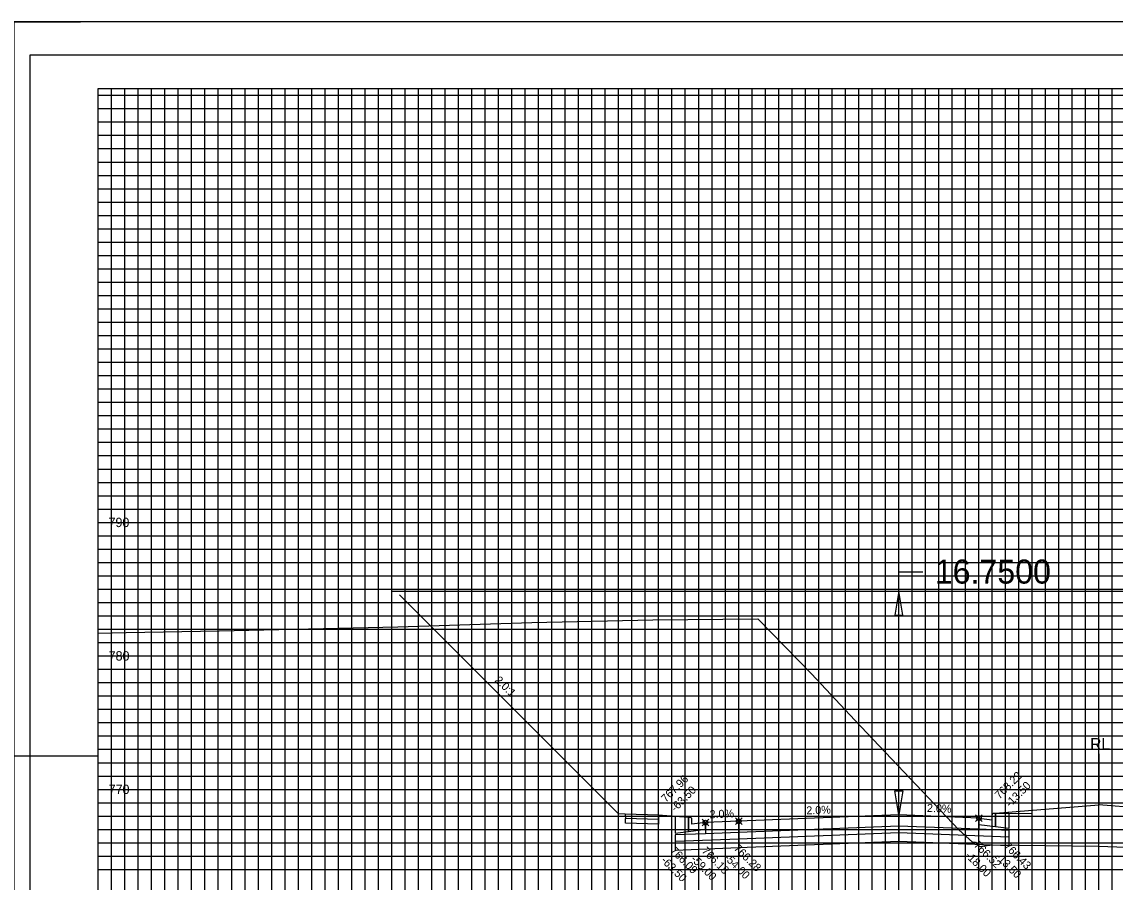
# Model space of a CAD drawing. Extents: x 578243 to 601557, y 174899 to 175559.
# Drawn here: x 600198.4 to 600362.3, y 174989.9 to 175118.8 of the extents above; entities that cross this region are included whole.
import ezdxf

# ---------------------------------------------------------------- set-up
doc = ezdxf.new("R2010")
doc.units = 0
for name, color, linetype in [('E_PROF_Grid', 7, 'Continuous'), ('E_PROF_GridMin', 7, 'Continuous'), ('P_CRDR_Label', 7, 'Continuous'), ('P_CRDR_Link', 7, 'Continuous'), ('P_E_XS_Ground', 7, 'Continuous'), ('P_RW_SlopeIntercepts', 7, 'Continuous'), ('P_XS_Text', 7, 'Continuous'), ('PLT_Sheet_Border', 7, 'Continuous'), ('PLT_Sheet_Info', 7, 'Continuous')]:
    doc.layers.add(name, color=color, linetype=linetype)

msp = doc.modelspace()

# ---------------------------------------------------------------- linework, layer by layer
at = {"layer": 'E_PROF_Grid'}
for p, q in [((600219.84, 174913.8), (600219.84, 175108.8)), ((600229.84, 174913.8), (600229.84, 175108.8)), ((600239.84, 174913.8), (600239.84, 175108.8)), ((600249.84, 174913.8), (600249.84, 175108.8)), ((600259.84, 174913.8), (600259.84, 175108.8)), ((600269.84, 174913.8), (600269.84, 175108.8)), ((600279.84, 174913.8), (600279.84, 175108.8)), ((600289.84, 174913.8), (600289.84, 175108.8)), ((600299.84, 174913.8), (600299.84, 175108.8)), ((600309.84, 174913.8), (600309.84, 175108.8)), ((600319.84, 174913.8), (600319.84, 175108.8)), ((600329.84, 174913.8), (600329.84, 175108.8)), ((600339.84, 174913.8), (600339.84, 175108.8)), ((600349.84, 174913.8), (600349.84, 175108.8)), ((600359.84, 174913.8), (600359.84, 175108.8)), ((600209.84, 175103.8), (600524.84, 175103.8)), ((600209.84, 175093.8), (600524.84, 175093.8)), ((600209.84, 175083.8), (600524.84, 175083.8)), ((600209.84, 175073.8), (600524.84, 175073.8)), ((600209.84, 175063.8), (600524.84, 175063.8)), ((600209.84, 175053.8), (600524.84, 175053.8)), ((600209.84, 175043.8), (600524.84, 175043.8)), ((600209.84, 175033.8), (600524.84, 175033.8)), ((600209.84, 175023.8), (600524.84, 175023.8)), ((600209.84, 175013.8), (600524.84, 175013.8)), ((600209.84, 175003.8), (600524.84, 175003.8)), ((600209.84, 174993.8), (600524.84, 174993.8))]:
    msp.add_line(p, q, dxfattribs=at)
at = {"layer": 'E_PROF_GridMin'}
for p, q in [((600211.84, 174913.8), (600211.84, 175108.8)), ((600213.84, 174913.8), (600213.84, 175108.8)), ((600215.84, 174913.8), (600215.84, 175108.8)), ((600217.84, 174913.8), (600217.84, 175108.8)), ((600221.84, 174913.8), (600221.84, 175108.8)), ((600223.84, 174913.8), (600223.84, 175108.8)), ((600225.84, 174913.8), (600225.84, 175108.8)), ((600227.84, 174913.8), (600227.84, 175108.8)), ((600231.84, 174913.8), (600231.84, 175108.8)), ((600233.84, 174913.8), (600233.84, 175108.8)), ((600235.84, 174913.8), (600235.84, 175108.8)), ((600237.84, 174913.8), (600237.84, 175108.8)), ((600241.84, 174913.8), (600241.84, 175108.8)), ((600243.84, 174913.8), (600243.84, 175108.8)), ((600245.84, 174913.8), (600245.84, 175108.8)), ((600247.84, 174913.8), (600247.84, 175108.8)), ((600251.84, 174913.8), (600251.84, 175108.8)), ((600253.84, 174913.8), (600253.84, 175108.8)), ((600255.84, 174913.8), (600255.84, 175108.8)), ((600257.84, 174913.8), (600257.84, 175108.8)), ((600261.84, 174913.8), (600261.84, 175108.8)), ((600263.84, 174913.8), (600263.84, 175108.8)), ((600265.84, 174913.8), (600265.84, 175108.8)), ((600267.84, 174913.8), (600267.84, 175108.8)), ((600271.84, 174913.8), (600271.84, 175108.8)), ((600273.84, 174913.8), (600273.84, 175108.8)), ((600275.84, 174913.8), (600275.84, 175108.8)), ((600277.84, 174913.8), (600277.84, 175108.8)), ((600281.84, 174913.8), (600281.84, 175108.8)), ((600283.84, 174913.8), (600283.84, 175108.8)), ((600285.84, 174913.8), (600285.84, 175108.8)), ((600287.84, 174913.8), (600287.84, 175108.8)), ((600291.84, 174913.8), (600291.84, 175108.8)), ((600293.84, 174913.8), (600293.84, 175108.8)), ((600295.84, 174913.8), (600295.84, 175108.8)), ((600297.84, 174913.8), (600297.84, 175108.8)), ((600301.84, 174913.8), (600301.84, 175108.8)), ((600303.84, 174913.8), (600303.84, 175108.8)), ((600305.84, 174913.8), (600305.84, 175108.8)), ((600307.84, 174913.8), (600307.84, 175108.8)), ((600311.84, 174913.8), (600311.84, 175108.8)), ((600313.84, 174913.8), (600313.84, 175108.8)), ((600315.84, 174913.8), (600315.84, 175108.8)), ((600317.84, 174913.8), (600317.84, 175108.8)), ((600321.84, 174913.8), (600321.84, 175108.8)), ((600323.84, 174913.8), (600323.84, 175108.8)), ((600325.84, 174913.8), (600325.84, 175108.8)), ((600327.84, 174913.8), (600327.84, 175108.8)), ((600331.84, 174913.8), (600331.84, 175108.8)), ((600333.84, 174913.8), (600333.84, 175108.8)), ((600335.84, 174913.8), (600335.84, 175108.8)), ((600337.84, 174913.8), (600337.84, 175108.8)), ((600341.84, 174913.8), (600341.84, 175108.8)), ((600343.84, 174913.8), (600343.84, 175108.8)), ((600345.84, 174913.8), (600345.84, 175108.8)), ((600347.84, 174913.8), (600347.84, 175108.8)), ((600351.84, 174913.8), (600351.84, 175108.8)), ((600353.84, 174913.8), (600353.84, 175108.8)), ((600355.84, 174913.8), (600355.84, 175108.8)), ((600357.84, 174913.8), (600357.84, 175108.8)), ((600361.84, 174913.8), (600361.84, 175108.8)), ((600209.84, 175107.8), (600524.84, 175107.8)), ((600209.84, 175105.8), (600524.84, 175105.8)), ((600209.84, 175101.8), (600524.84, 175101.8)), ((600209.84, 175099.8), (600524.84, 175099.8)), ((600209.84, 175097.8), (600524.84, 175097.8)), ((600209.84, 175095.8), (600524.84, 175095.8)), ((600209.84, 175091.8), (600524.84, 175091.8)), ((600209.84, 175089.8), (600524.84, 175089.8)), ((600209.84, 175087.8), (600524.84, 175087.8)), ((600209.84, 175085.8), (600524.84, 175085.8)), ((600209.84, 175081.8), (600524.84, 175081.8)), ((600209.84, 175079.8), (600524.84, 175079.8)), ((600209.84, 175077.8), (600524.84, 175077.8)), ((600209.84, 175075.8), (600524.84, 175075.8)), ((600209.84, 175071.8), (600524.84, 175071.8)), ((600209.84, 175069.8), (600524.84, 175069.8)), ((600209.84, 175067.8), (600524.84, 175067.8)), ((600209.84, 175065.8), (600524.84, 175065.8)), ((600209.84, 175061.8), (600524.84, 175061.8)), ((600209.84, 175059.8), (600524.84, 175059.8)), ((600209.84, 175057.8), (600524.84, 175057.8)), ((600209.84, 175055.8), (600524.84, 175055.8)), ((600209.84, 175051.8), (600524.84, 175051.8)), ((600209.84, 175049.8), (600524.84, 175049.8)), ((600209.84, 175047.8), (600524.84, 175047.8)), ((600209.84, 175045.8), (600524.84, 175045.8)), ((600209.84, 175041.8), (600524.84, 175041.8)), ((600209.84, 175039.8), (600524.84, 175039.8)), ((600209.84, 175037.8), (600524.84, 175037.8)), ((600209.84, 175035.8), (600524.84, 175035.8)), ((600209.84, 175031.8), (600524.84, 175031.8)), ((600209.84, 175029.8), (600524.84, 175029.8)), ((600209.84, 175027.8), (600524.84, 175027.8)), ((600209.84, 175025.8), (600524.84, 175025.8)), ((600209.84, 175021.8), (600524.84, 175021.8)), ((600209.84, 175019.8), (600524.84, 175019.8)), ((600209.84, 175017.8), (600524.84, 175017.8)), ((600209.84, 175015.8), (600524.84, 175015.8)), ((600209.84, 175011.8), (600524.84, 175011.8)), ((600209.84, 175009.8), (600524.84, 175009.8)), ((600209.84, 175007.8), (600524.84, 175007.8)), ((600209.84, 175005.8), (600524.84, 175005.8)), ((600209.84, 175001.8), (600524.84, 175001.8)), ((600209.84, 174999.8), (600524.84, 174999.8)), ((600209.84, 174997.8), (600524.84, 174997.8)), ((600209.84, 174995.8), (600524.84, 174995.8)), ((600209.84, 174991.8), (600524.84, 174991.8))]:
    msp.add_line(p, q, dxfattribs=at)
at = {"layer": 'P_CRDR_Label'}
for p, q in [((600359.84, 175009.11), (600359.84, 175001.49)), ((600341.35, 174999), (600342.34, 174999.99)), ((600341.35, 174999.99), (600342.34, 174999)), ((600300.35, 174998.32), (600301.34, 174999.31)), ((600300.35, 174999.31), (600301.34, 174998.32)), ((600305.35, 174998.52), (600306.34, 174999.51)), ((600305.35, 174999.51), (600306.34, 174998.52))]:
    msp.add_line(p, q, dxfattribs=at)
for centre in [(600341.84, 174999.5), (600300.84, 174998.82), (600305.84, 174999.02)]:
    msp.add_circle(centre, 0.35, dxfattribs=at)
at = {"layer": 'P_CRDR_Link'}
for p, q in [((600254.99, 175032.96), (600287.84, 175000.11)), ((600344.34, 175000.25), (600359.84, 175001.49)), ((600344.34, 175000.25), (600359.84, 175001.49)), ((600375.34, 175000.25), (600359.84, 175001.49)), ((600375.34, 175000.25), (600359.84, 175001.49)), ((600288.84, 175000.08), (600287.84, 175000.11)), ((600288.84, 175000.08), (600287.84, 175000.11)), ((600293.84, 174999.93), (600288.84, 175000.08)), ((600293.84, 174999.93), (600288.84, 175000.08)), ((600288.84, 175000.08), (600288.85, 174999.41)), ((600296.34, 174999.73), (600293.84, 174999.93)), ((600296.34, 174999.73), (600293.84, 174999.93)), ((600293.84, 174999.93), (600293.84, 174999.26)), ((600329.84, 174999.98), (600305.84, 174999.02)), ((600341.84, 174999.5), (600329.84, 174999.98)), ((600329.84, 174999.98), (600329.84, 174998.31)), ((600329.84, 174999.98), (600329.84, 174998.31)), ((600343.84, 174999.25), (600343.85, 174999.93)), ((600343.84, 174999.25), (600343.85, 174999.93)), ((600343.85, 174999.93), (600343.88, 175000.09)), ((600343.85, 174999.93), (600343.88, 175000.09)), ((600343.88, 175000.09), (600343.94, 175000.2)), ((600343.88, 175000.09), (600343.94, 175000.2)), ((600343.94, 175000.2), (600344.02, 175000.25)), ((600343.94, 175000.2), (600344.02, 175000.25)), ((600344.02, 175000.25), (600344.34, 175000.25)), ((600344.02, 175000.25), (600344.34, 175000.25)), ((600344.34, 175000.25), (600344.34, 174998.18)), ((600344.34, 175000.25), (600346.34, 175000.23)), ((600344.34, 174998.18), (600344.34, 175000.25)), ((600346.34, 175000.23), (600346.34, 174997.93)), ((600346.34, 175000.23), (600346.34, 174997.93)), ((600346.34, 175000.23), (600346.34, 174997.93)), ((600346.34, 175000.23), (600349.84, 175000.2)), ((600346.34, 175000.23), (600349.84, 175000.2)), ((600293.84, 174999.26), (600288.85, 174999.41)), ((600288.85, 174998.75), (600288.85, 174999.41)), ((600293.83, 174998.6), (600288.85, 174998.75)), ((600293.84, 174999.26), (600293.83, 174998.6)), ((600298.34, 174999.57), (600296.34, 174999.73)), ((600296.34, 174999.73), (600296.34, 174997.25)), ((600296.34, 174999.73), (600296.34, 174997.25)), ((600296.34, 174999.73), (600296.34, 174997.25)), ((600298.66, 174999.57), (600298.34, 174999.57)), ((600298.66, 174999.57), (600298.34, 174999.57)), ((600298.34, 174999.57), (600298.34, 174997.5)), ((600298.34, 174997.5), (600298.34, 174999.57)), ((600298.74, 174999.52), (600298.66, 174999.57)), ((600298.74, 174999.52), (600298.66, 174999.57)), ((600298.8, 174999.41), (600298.74, 174999.52)), ((600298.8, 174999.41), (600298.74, 174999.52)), ((600298.83, 174999.25), (600298.8, 174999.41)), ((600298.83, 174999.25), (600298.8, 174999.41)), ((600298.84, 174998.57), (600298.83, 174999.25)), ((600298.84, 174998.57), (600298.83, 174999.25)), ((600300.84, 174998.82), (600298.84, 174998.57)), ((600300.84, 174998.82), (600298.84, 174998.57)), ((600305.84, 174999.02), (600300.84, 174998.82)), ((600300.84, 174998.82), (600300.84, 174997.15)), ((600300.84, 174997.82), (600300.84, 174998.82)), ((600305.84, 174999.02), (600305.84, 174997.35)), ((600305.84, 174999.02), (600305.84, 174997.35)), ((600329.84, 174998.31), (600305.84, 174997.35)), ((600341.84, 174997.83), (600329.84, 174998.31)), ((600329.84, 174998.31), (600329.84, 174997.31)), ((600329.84, 174998.31), (600329.84, 174997.31)), ((600341.84, 174999.5), (600343.84, 174999.25)), ((600341.84, 174999.5), (600343.84, 174999.25)), ((600341.84, 174998.5), (600341.84, 174999.5)), ((600341.84, 174999.5), (600341.84, 174997.83)), ((600344.34, 174998.18), (600341.84, 174998.5)), ((600344.34, 174998.18), (600341.84, 174998.5)), ((600346.34, 174997.93), (600344.34, 174998.18)), ((600296.34, 174997.25), (600298.34, 174997.5)), ((600300.84, 174997.15), (600296.34, 174996.97)), ((600296.34, 174996.97), (600296.34, 174995.97)), ((600298.34, 174997.5), (600300.84, 174997.82)), ((600298.34, 174997.5), (600300.84, 174997.82)), ((600305.84, 174997.35), (600300.84, 174997.15)), ((600305.84, 174997.35), (600305.84, 174996.35)), ((600305.84, 174997.35), (600305.84, 174996.35)), ((600329.84, 174997.31), (600305.84, 174996.35)), ((600346.34, 174996.65), (600329.84, 174997.31)), ((600329.84, 174997.31), (600329.84, 174995.98)), ((600329.84, 174997.31), (600329.84, 174995.98)), ((600346.34, 174997.65), (600341.84, 174997.83)), ((600346.34, 174997.65), (600346.34, 174996.65)), ((600346.34, 174996.65), (600346.34, 174995.32)), ((600305.84, 174996.35), (600296.34, 174995.97)), ((600296.34, 174995.97), (600296.34, 174994.64)), ((600305.84, 174995.02), (600296.34, 174994.64)), ((600305.84, 174996.35), (600305.84, 174995.02)), ((600305.84, 174996.35), (600305.84, 174995.02)), ((600329.84, 174995.98), (600305.84, 174995.02)), ((600346.34, 174995.32), (600329.84, 174995.98))]:
    msp.add_line(p, q, dxfattribs=at)
at = {"layer": 'P_E_XS_Ground'}
msp.add_lwpolyline([(600209.84, 175027.22), (600214.04, 175027.32), (600227.99, 175027.54), (600254.75, 175028.15), (600274.81, 175028.81), (600292.99, 175029.21), (600308.7, 175029.35), (600316.73, 175021.12), (600323.27, 175014.17), (600338.84, 174997.75), (600340.9, 174995.91), (600340.9, 174995.91), (600341.32, 174995.91), (600341.9, 174995.24), (600343.9, 174995.49), (600347.84, 174995.44), (600359.84, 174995.3), (600371.84, 174994.82)], dxfattribs=at)
at = {"layer": 'P_RW_SlopeIntercepts'}
for p, q in [((600329.84, 175036.4), (600333.44, 175036.4)), ((600329.84, 174999.98), (600329.84, 175036.4)), ((600253.84, 175033.48), (600489.84, 175033.48)), ((600329.84, 175033.48), (600329.24, 175029.88)), ((600330.44, 175029.88), (600329.84, 175033.48)), ((600329.24, 175029.88), (600330.44, 175029.88)), ((600329.24, 175003.58), (600330.44, 175003.58)), ((600329.84, 174999.98), (600329.24, 175003.58)), ((600330.44, 175003.58), (600329.84, 174999.98))]:
    msp.add_line(p, q, dxfattribs=at)
at = {"layer": 'PLT_Sheet_Border'}
for points in [[(600197.19, 174898.8), (600537.19, 174898.8), (600537.19, 175118.8), (600197.19, 175118.8)], [(600199.59, 174903.8), (600530.59, 174903.8), (600530.59, 175113.8), (600199.59, 175113.8)]]:
    msp.add_lwpolyline(points, close=True, dxfattribs=at)
at = {"layer": 'PLT_Sheet_Info'}
for p, q in [((600197.19, 175118.8), (600207.19, 175118.8)), ((600209.84, 175108.8), (600524.84, 175108.8)), ((600209.84, 174908.8), (600209.84, 175108.8)), ((600197.19, 175008.8), (600209.84, 175008.8))]:
    msp.add_line(p, q, dxfattribs=at)

# ---------------------------------------------------------------- texts
at = {"layer": 'P_CRDR_Label'}
for s, rotation, p in [('2.0:1', 315.8532, (600269.19, 175020.04)), ('768.22', 45, (600344.93, 175002.27)), ('767.96', 45, (600294.93, 175001.77)), ('-13.50', 45, (600346.52, 175001.04)), ('-63.50', 45, (600296.35, 175000.36)), ('2.0%', 357.7094, (600334.05, 175000.43)), ('2.0%', 2.2906, (600301.5, 174999.46)), ('2.0%', 2.2906, (600316, 175000.04)), ('766.09', 315, (600295.49, 174994.49)), ('766.18', 315, (600300.2, 174994.46)), ('766.28', 315, (600305.02, 174994.84)), ('766.52', 315, (600340.99, 174995.35)), ('766.43', 315, (600345.49, 174995.17)), ('-63.50', 315, (600294.11, 174993.05)), ('-59.00', 315, (600298.58, 174993.26)), ('-54.00', 315, (600303.58, 174993.46)), ('-18.00', 315, (600339.73, 174993.79)), ('-13.50', 315, (600344.26, 174993.58))]:
    msp.add_text(s, height=1.2, rotation=rotation, dxfattribs=at).set_placement(p)
msp.add_text('RL', height=1.75, dxfattribs=at).set_placement((600358.52, 175009.74))
at = {"layer": 'P_RW_SlopeIntercepts'}
msp.add_text('16.7500', height=3.6, dxfattribs=at).set_placement((600335.24, 175034.63))
at = {"layer": 'P_XS_Text'}
for s, p in [('790', (600211.38, 175043.1)), ('780', (600211.4, 175023.1)), ('770', (600211.4, 175003.1))]:
    msp.add_text(s, height=1.4, rotation=360, dxfattribs=at).set_placement(p)

doc.saveas('drawing.dxf')
